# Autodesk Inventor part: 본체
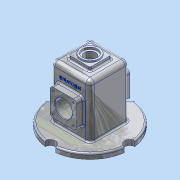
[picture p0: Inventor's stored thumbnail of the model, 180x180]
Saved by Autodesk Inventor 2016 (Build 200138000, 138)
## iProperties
Created: 2018-07
Part Number: 본체
Material: 알루미늄 6061
Document SubType Name: Modeling
Designer: 605-03
Density: 2.7 g/cm^3
Appearance: 알루미늄 - 평지
Mass: 909.309 g
Surface Area: 1017.52 cm^2
Volume: 336.781 cm^3
Author: 605-03
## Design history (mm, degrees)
sketch "스케치1"
  geometry: L1 (-37, -37)-(37, -37); L2 (37, -37)-(37, 37); L3 (37, 37)-(-37, 37); L4 (-37, 37)-(-37, -37); L5 (-37, -37)-(37, 37); L6 (37, -37)-(-37, 37); 1 further point
  constraints: 12 end point, 2 midpoint, 2 parallel, 1 horizontal, 1 perpendicular
  dimensions: "d0" = 74 distance of L3.end L2.end; "d1" = 74 distance of L2.end L1.end
extrude "돌출1" new body sketch "스케치1" distance "d2" = 110; taper "d3" = 0 deg
fillet "모깎기1" dims "d24" = 8
feature "쉘1" dims "d4" = 5
sketch "스케치2"
  geometry: L1 (-20, -20)-(20, -20); L2 (20, -20)-(20, 20); L3 (20, 20)-(-20, 20); L4 (-20, 20)-(-20, -20); L5 (-20, -20)-(20, 20); L6 (20, -20)-(-20, 20); 1 further point
  constraints: 12 end point, 2 midpoint, 2 parallel, 1 horizontal, 1 perpendicular
  dimensions: "d5" = 40 distance of L3.end L2.end; "d6" = 40 distance of L2.end L1.end
extrude "돌출2" join sketch "스케치2" distance "d7" = 7; taper "d8" = 0 deg
sketch "스케치3"
  geometry: C1 r 17.5 at (0, 0); 1 further point
  constraints: 1 centre point, 1 coincident
  dimensions: "d9" = 35 diameter of C1
extrude "돌출3" join sketch "스케치3" distance "d10" = 3; taper "d11" = 0 deg
hole "구멍1" diameter "d14" = 21; stored, may be unused: countersink angle "d18" = 90 deg, drill point angle "d20" = 118 deg; dims "d12" = 10, "d13" = 10, "d15" = 6, "d16" = 28, "d17" = 4, "d19" = 8
sketch "스케치4"
  geometry: C1 r 75 at (0, 0); 1 further point
  constraints: 1 centre point, 1 coincident
  dimensions: "d21" = 150 diameter of C1
extrude "돌출4" cut sketch "스케치4" distance "d22" = 10; taper "d23" = 0 deg
sketch "스케치5"
  geometry: C1 r 75 at (0, 0); 1 further point
  constraints: 1 centre point, 1 coincident
  dimensions: "d25" = 150 diameter of C1
extrude "돌출5" join sketch "스케치5" distance "d26" = 10; taper "d27" = 0 deg
sketch "스케치6"
  geometry: L1 (-37, -37)-(-37, 37) reference; L2 (-37, -37)-(-37, 37) reference; L3 (-37, 37)-(37, 37) reference; L4 (-37, 37)-(37, 37) reference; L5 (37, -37)-(-37, -37) reference; L6 (37, -37)-(-37, -37) reference; L7 (37, 37)-(37, -37) reference; L8 (37, 37)-(37, -37) reference; L9 (-32, 32)-(32, 32); L10 (32, 32)-(32, -32); L11 (32, -32)-(-32, -32); L12 (-32, -32)-(-32, 32); 1 further point
  constraints: 8 end point, 4 parallel
  dimensions: "d28" = 5 distance between parallel lines of L3 L9; "d29" = 5 distance between parallel lines of L7 L10; "d30" = 5 distance between parallel lines of L5 L11; "d31" = 5 distance between parallel lines of L1 L12
extrude "돌출6" cut sketch "스케치6" distance "d32" = 10; taper "d33" = 0 deg
sketch "스케치7"
  geometry: L1 (25, 30)-(-25, 30); L2 (-25, 30)-(-25, 80); L3 (-25, 80)-(25, 80); L4 (25, 80)-(25, 30); L5 (25, 30)-(-25, 80); L6 (-25, 30)-(25, 80); L7 (-32, 0)-(32, 0) reference; L8 (-37, 10)-(-37, 102) reference; 2 further points
  constraints: 12 end point, 2 midpoint, 2 parallel, 1 horizontal, 1 perpendicular
  dimensions: "d34" = 50 distance of L2.end L3.end; "d35" = 50 distance of L1.end L2.end; "d36" = 55 distance from line of L7 point (0, 55); "d37" = 37 distance from line of L8 point (0, 55)
extrude "돌출7" join sketch "스케치7" stored distance "d38" = 100; taper "d39" = 0 deg
sketch "스케치8"
  geometry: L1 (32, -32)-(32, 32) reference; L2 (32, 32)-(-32, 32) reference; L3 (-32, 32)-(-32, -32) reference; L4 (-32, -32)-(32, -32) reference; 1 further point
extrude "돌출8" cut sketch "스케치8" distance "d40" = 100; taper "d41" = 0 deg
sketch "스케치9"
  geometry: L1 (0, 0)-(0, 99.913); L2 (-50, 80)-(-50, 30) reference; L3 (-50, 55)-(50, 55); L4 (50, 30)-(50, 80) reference; L5 (32, 0)-(32, 102) reference; L6 (32, 30.022)-(25, 32.569); L7 (25, 32.569)-(25, 55); L8 (32, 30.022)-(32, 55); L9 (-32, 30.022)-(-25, 32.569); L10 (-25, 32.569)-(-25, 55); L11 (-32, 30.022)-(-32, 55)
  constraints: 16 end point, 5 point on line, 2 midpoint, 2 symmetric about line, 1 collinear, 1 parallel, 1 vertical
  dimensions: "d42" = 110 deg angle of L5 L6; "d43" = 7 distance between parallel lines of L5 L7
revolve "회전1" sketch "스케치9" stored, may be unused: angle "d44" = 90 deg
sketch "스케치10"
  geometry: C1 r 24.978 at (0, -55) reference; 1 further point
hole "구멍2" sketch "스케치10" at (0, -55) diameter "d45" = 32; stored, may be unused: countersink angle "d49" = 90 deg, drill point angle "d51" = 118 deg; dims "d46" = 6, "d47" = 28, "d48" = 4, "d50" = 8
fillet "모깎기2" dims "d52" = 8
fillet "모깎기3" dims "d53" = 3
sketch "스케치11"
  geometry: C1 r 10 at (0.041, 75); 3 further points
  constraints: 1 centre point, 4 other
  dimensions: "d54" = 20 diameter of C1
extrude "돌출9" cut sketch "스케치11" stored distance "d55" = 0; taper "d56" = 0 deg
fillet "모깎기4" dims "d60" = 6
fillet "모깎기5" dims "d61" = 3
fillet "모깎기6" dims "d62" = 3
sketch "스케치12"
  geometry: A1 r 6 centre (-19, 74) between (-19, 80) and (-25, 74) reference; A2 r 6 centre (19, 74) between (25, 74) and (19, 80) reference; A3 r 6 centre (19, 36) between (19, 30) and (25, 36) reference; A4 r 6 centre (-19, 36) between (-25, 36) and (-19, 30) reference; 1 further point
hole "구멍3" sketch "스케치12" at (19, 74), (-19, 74), (-19, 36), (19, 36) diameter "d63" = 3.242; stored, may be unused: countersink angle "d67" = 90 deg, drill point angle "d69" = 118 deg; dims "d64" = 8, "d65" = 28, "d66" = 4, "d68" = 10
sketch "스케치13"
  geometry: L1 (66, -89)-(66, 0) reference; L2 (46.5, 18)-(11.5, 18) reference; 2 further points
  constraints: 1 other
  dimensions: "d70" = 37 distance from line of L1 point (29, -12); "d71" = 30 distance from line of L2 point (29, -12)
feature "엠보싱1" sketch "스케치13" dims "d0" = 74, "d1" = 74, "d72" = 0.5, "d73" = 0
chamfer "모따기1" distance "d74" = 1; stored, may be unused: second distance "d75" = 2, angle "d76" = 45 deg
sketch "스케치14"
  geometry: L1 (0, 140.697)-(81.914, 140.697); L2 (81.914, 140.697)-(81.914, -37.986); L3 (81.914, -37.986)-(0, -37.986); L4 (0, -37.986)-(0, 140.697); 1 further point
  constraints: 8 end point, 2 parallel, 1 horizontal, 1 perpendicular
extrude "돌출10" cut sketch "스케치14" stored distance "d77" = 0; taper "d78" = 0 deg
node "솔리드1"
pattern_circular "원형 패턴1" dims angle "d58" = 360 deg
mirror "대칭1"
node "투영된 루프1"
node "투영된 루프2"
node "투영된 루프3"
node "투영된 루프4"
